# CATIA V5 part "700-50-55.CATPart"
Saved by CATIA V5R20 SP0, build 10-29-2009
Part number: 700-50-55
Revision: ANY
Definition: UNKNOWN
Nomenclature: 700-50-55
Source: Unknown
Bounding box of the stored display mesh (mm): x -25 to 25, y 0 to 55, z -25 to 25
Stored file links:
  C:\Users\Utente\Desktop\IO LAVORO\3D X SITO CF\X SITO\700\700-50-55.CATPart
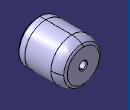
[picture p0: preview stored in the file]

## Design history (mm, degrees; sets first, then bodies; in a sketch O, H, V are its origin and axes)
Body1 "Rivoluzione1" (main body)
  Solid1: solid without history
